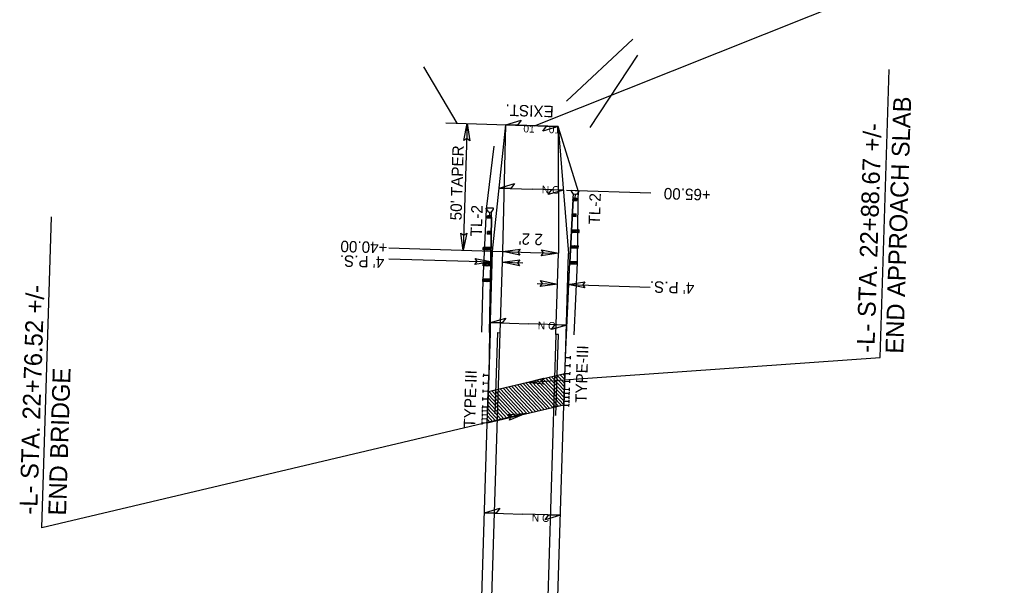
# Model space of a CAD drawing. Extents: x 1515198 to 1515601, y 565062 to 565830.
# Drawn here: x 1515204.5 to 1515593.5, y 565342 to 565565 of the extents above; entities that cross this region are included whole.
import ezdxf

# ---------------------------------------------------------------- set-up
doc = ezdxf.new("R2010")
doc.units = 0
for name, color, linetype in [('Default', 7, 'Continuous'), ('Old_Level_1', 7, 'Continuous'), ('Old_Level_3', 7, 'Continuous'), ('Prop Approach Slab', 7, 'Continuous'), ('Prop Approach Slab Hatching', 7, 'Continuous'), ('Prop Dimension', 7, 'Continuous'), ('Prop Dimension Text', 7, 'Continuous'), ('Prop EOT', 7, 'Continuous'), ('Prop Guardrail', 7, 'Continuous'), ('Prop Guardrail Anchor Unit CELL', 7, 'Continuous'), ('Prop Horizontal Alignment Curve and Spiral Data', 7, 'Continuous'), ('Prop Horizontal Alignment Tick Small', 7, 'Continuous'), ('Prop Lane Lines', 7, 'Continuous'), ('Prop Paved Shoulder', 7, 'Continuous'), ('Prop Roadway Bridge', 7, 'Continuous'), ('Prop SBG', 7, 'Continuous'), ('Prop Structure Anchor Unit CELL', 7, 'Continuous'), ('Prop Superelevation  Arrow CELL', 7, 'Continuous'), ('Prop Superelevation Label', 7, 'Continuous'), ('Prop Terminator CELL', 7, 'Continuous')]:
    doc.layers.add(name, color=color, linetype=linetype)

msp = doc.modelspace()

# ---------------------------------------------------------------- linework, layer by layer
at = {"layer": 'Default'}
msp.add_lwpolyline([(1515421.77, 565431.67), (1515419.93, 565431.83), (1515419.74, 565432.08)], dxfattribs=at)
at = {"layer": 'Old_Level_1'}
for p, q in [((1515424.77, 565497.19), (1515416.89, 565522.45)), ((1515388.56, 565490.28), (1515391.55, 565515.2)), ((1515424.39, 565469.19), (1515424.68, 565494.19)), ((1515424.68, 565494.19), (1515424.77, 565497.19)), ((1515388.46, 565487.28), (1515388.56, 565490.28)), ((1515387.18, 565462.31), (1515388.46, 565487.28)), ((1515423.07, 565440.7), (1515424.39, 565469.19)), ((1515386.76, 565441.84), (1515387.18, 565462.31))]:
    msp.add_line(p, q, dxfattribs=at)
at = {"layer": 'Old_Level_3'}
for p, q in [((1515421.41, 565469.28), (1515422.69, 565494.25)), ((1515390.17, 565462.22), (1515390.45, 565487.21)), ((1515420.08, 565440.79), (1515421.41, 565469.28)), ((1515389.75, 565441.74), (1515390.17, 565462.22)), ((1515390.17, 565462.22), (1515390.17, 565462.22))]:
    msp.add_line(p, q, dxfattribs=at)
at = {"layer": 'Prop Approach Slab'}
msp.add_lwpolyline([(1515388.83, 565405.98), (1515389.22, 565418.4), (1515419.45, 565425.49), (1515419.06, 565413.07)], close=True, dxfattribs=at)
at = {"layer": 'Prop Approach Slab Hatching'}
for p, q in [((1515419.11, 565414.63), (1515410.82, 565423.47)), ((1515419.16, 565416.05), (1515411.94, 565423.73)), ((1515419.2, 565417.46), (1515413.07, 565423.99)), ((1515419.25, 565418.87), (1515414.19, 565424.26)), ((1515419.29, 565420.29), (1515415.31, 565424.52)), ((1515419.33, 565421.7), (1515416.44, 565424.78)), ((1515419.38, 565423.11), (1515417.56, 565425.05)), ((1515419.42, 565424.53), (1515418.69, 565425.31)), ((1515403.44, 565409.41), (1515393.96, 565419.51)), ((1515404.57, 565409.67), (1515395.08, 565419.77)), ((1515405.69, 565409.94), (1515396.2, 565420.04)), ((1515406.81, 565410.2), (1515397.33, 565420.3)), ((1515407.94, 565410.46), (1515398.45, 565420.56)), ((1515409.06, 565410.73), (1515399.58, 565420.83)), ((1515410.19, 565410.99), (1515400.7, 565421.09)), ((1515411.31, 565411.26), (1515401.82, 565421.36)), ((1515412.43, 565411.52), (1515402.95, 565421.62)), ((1515413.56, 565411.78), (1515404.07, 565421.88)), ((1515414.68, 565412.05), (1515405.2, 565422.15)), ((1515415.81, 565412.31), (1515406.32, 565422.41)), ((1515416.93, 565412.57), (1515407.45, 565422.67)), ((1515418.06, 565412.84), (1515408.57, 565422.94)), ((1515419.07, 565413.22), (1515409.69, 565423.2)), ((1515396.7, 565407.83), (1515389.14, 565415.87)), ((1515397.82, 565408.09), (1515389.18, 565417.29)), ((1515398.94, 565408.35), (1515389.46, 565418.45)), ((1515400.07, 565408.62), (1515390.58, 565418.72)), ((1515401.19, 565408.88), (1515391.71, 565418.98)), ((1515402.32, 565409.15), (1515392.83, 565419.25)), ((1515393.32, 565407.03), (1515389, 565411.63)), ((1515394.45, 565407.3), (1515389.05, 565413.05)), ((1515395.57, 565407.56), (1515389.09, 565414.46)), ((1515391.08, 565406.51), (1515388.92, 565408.81)), ((1515392.2, 565406.77), (1515388.96, 565410.22)), ((1515389.95, 565406.24), (1515388.87, 565407.39))]:
    msp.add_line(p, q, dxfattribs=at)
at = {"layer": 'Prop Dimension'}
for p, q in [((1515372.53, 565524.32), (1515416.85, 565522.93)), ((1515380.92, 565524.06), (1515379.35, 565474.08)), ((1515420.03, 565497.82), (1515453.36, 565496.78)), ((1515350.07, 565475), (1515394.95, 565473.6)), ((1515350.07, 565470.78), (1515390.82, 565469.5)), ((1515394.95, 565473.6), (1515405.94, 565473.25)), ((1515405.94, 565473.25), (1515416.94, 565472.91)), ((1515394.82, 565469.38), (1515402.81, 565469.13)), ((1515408.56, 565461.01), (1515416.56, 565460.76)), ((1515420.55, 565460.64), (1515453.02, 565459.62))]:
    msp.add_line(p, q, dxfattribs=at)
at = {"layer": 'Prop EOT'}
for p, q in [((1515394.95, 565473.6), (1515396.21, 565523.58)), ((1515416.85, 565522.93), (1515396.21, 565523.58)), ((1515416.85, 565522.93), (1515416.94, 565472.91)), ((1515393.95, 565441.61), (1515394.95, 565473.6)), ((1515415.94, 565440.92), (1515416.94, 565472.91)), ((1515391.94, 565409.66), (1515392.95, 565441.64)), ((1515392.95, 565441.64), (1515393.95, 565441.61)), ((1515415.93, 565408.91), (1515416.93, 565440.89)), ((1515416.93, 565440.89), (1515415.94, 565440.92))]:
    msp.add_line(p, q, dxfattribs=at)
at = {"layer": 'Prop Guardrail'}
for p, q in [((1515419.93, 565440.8), (1515421.4, 565469.28)), ((1515390.18, 565462.21), (1515389.95, 565441.74)), ((1515389.95, 565441.74), (1515389.41, 565424.72)), ((1515419.65, 565431.82), (1515419.93, 565440.8))]:
    msp.add_line(p, q, dxfattribs=at)
at = {"layer": 'Prop Guardrail Anchor Unit CELL'}
for p, q in [((1515420.04, 565532.84), (1515446.25, 565557.32)), ((1515429.48, 565522.54), (1515448.17, 565551.03)), ((1515377, 565524.18), (1515363.88, 565546.42)), ((1515422, 565497.43), (1515422.01, 565497.74)), ((1515422.79, 565496.21), (1515422, 565497.43)), ((1515422.01, 565497.74), (1515424.95, 565497.59)), ((1515424.93, 565497.28), (1515424.02, 565496.15)), ((1515424.93, 565497.28), (1515424.95, 565497.59)), ((1515422.68, 565494.25), (1515421.4, 565469.28)), ((1515422.65, 565493.75), (1515422.7, 565494.75)), ((1515422.65, 565493.75), (1515424.22, 565494.67)), ((1515422.65, 565493.75), (1515424.17, 565493.67)), ((1515422.7, 565494.75), (1515424.22, 565494.67)), ((1515424.17, 565493.67), (1515422.7, 565494.75)), ((1515422.71, 565494.74), (1515422.79, 565496.21)), ((1515424.02, 565496.15), (1515422.79, 565496.21)), ((1515423.51, 565496.18), (1515423.43, 565494.71)), ((1515424.17, 565493.67), (1515424.22, 565494.67)), ((1515391.35, 565490.66), (1515388.41, 565490.69)), ((1515388.41, 565490.38), (1515388.41, 565490.69)), ((1515388.41, 565490.38), (1515389.25, 565489.2)), ((1515390.47, 565489.18), (1515391.35, 565490.35)), ((1515391.35, 565490.35), (1515391.35, 565490.66)), ((1515388.94, 565486.73), (1515388.95, 565487.73)), ((1515388.94, 565486.73), (1515390.47, 565487.71)), ((1515390.46, 565486.71), (1515388.94, 565486.73)), ((1515390.47, 565487.71), (1515388.95, 565487.73)), ((1515390.46, 565486.71), (1515388.95, 565487.73)), ((1515389.25, 565489.2), (1515390.47, 565489.18)), ((1515389.75, 565489.19), (1515389.74, 565487.72)), ((1515390.46, 565487.21), (1515390.18, 565462.21)), ((1515390.46, 565487.71), (1515390.47, 565489.18)), ((1515390.46, 565486.71), (1515390.47, 565487.71)), ((1515422.33, 565487.5), (1515422.38, 565488.5)), ((1515422.33, 565487.5), (1515423.9, 565488.43)), ((1515422.33, 565487.5), (1515423.85, 565487.43)), ((1515422.38, 565488.5), (1515423.9, 565488.43)), ((1515423.85, 565487.43), (1515422.38, 565488.5)), ((1515423.85, 565487.43), (1515423.9, 565488.43)), ((1515422.01, 565481.26), (1515422.06, 565482.26)), ((1515422.01, 565481.26), (1515423.58, 565482.18)), ((1515422.06, 565482.26), (1515425.09, 565482.11)), ((1515423.53, 565481.19), (1515422.06, 565482.26)), ((1515423.53, 565481.19), (1515423.58, 565482.18)), ((1515425.09, 565482.11), (1515423.53, 565481.19)), ((1515423.58, 565482.18), (1515425.04, 565481.11)), ((1515425.04, 565481.11), (1515425.09, 565482.11)), ((1515388.87, 565480.48), (1515388.88, 565481.48)), ((1515388.87, 565480.48), (1515390.4, 565481.46)), ((1515390.39, 565480.46), (1515388.87, 565480.48)), ((1515390.4, 565481.46), (1515388.88, 565481.48)), ((1515390.39, 565480.46), (1515388.88, 565481.48)), ((1515390.39, 565480.46), (1515390.4, 565481.46)), ((1515422.01, 565481.26), (1515425.04, 565481.11)), ((1515387.28, 565474.25), (1515387.29, 565475.25)), ((1515388.81, 565475.23), (1515387.28, 565474.25)), ((1515390.32, 565474.21), (1515387.28, 565474.25)), ((1515390.33, 565475.21), (1515387.29, 565475.25)), ((1515387.29, 565475.25), (1515388.8, 565474.23)), ((1515388.8, 565474.23), (1515388.81, 565475.23)), ((1515388.8, 565474.23), (1515390.33, 565475.21)), ((1515390.32, 565474.21), (1515388.81, 565475.23)), ((1515390.32, 565474.21), (1515390.33, 565475.21)), ((1515421.69, 565475.02), (1515421.74, 565476.02)), ((1515421.69, 565475.02), (1515423.26, 565475.94)), ((1515421.69, 565475.02), (1515424.72, 565474.87)), ((1515421.74, 565476.02), (1515424.77, 565475.86)), ((1515423.21, 565474.94), (1515421.74, 565476.02)), ((1515423.21, 565474.94), (1515423.26, 565475.94)), ((1515424.77, 565475.86), (1515423.21, 565474.94)), ((1515423.26, 565475.94), (1515424.72, 565474.87)), ((1515424.72, 565474.87), (1515424.77, 565475.86)), ((1515387.21, 565468), (1515387.22, 565469)), ((1515388.74, 565468.98), (1515387.21, 565468)), ((1515390.25, 565467.96), (1515387.21, 565468)), ((1515390.26, 565468.96), (1515387.22, 565469)), ((1515387.22, 565469), (1515388.73, 565467.98)), ((1515388.73, 565467.98), (1515388.74, 565468.98)), ((1515388.73, 565467.98), (1515390.26, 565468.96)), ((1515390.25, 565467.96), (1515388.74, 565468.98)), ((1515390.25, 565467.96), (1515390.26, 565468.96)), ((1515421.37, 565468.78), (1515421.42, 565469.78)), ((1515421.37, 565468.78), (1515422.94, 565469.7)), ((1515421.37, 565468.78), (1515424.4, 565468.62)), ((1515421.42, 565469.78), (1515424.45, 565469.62)), ((1515422.89, 565468.7), (1515421.42, 565469.78)), ((1515422.89, 565468.7), (1515422.94, 565469.7)), ((1515424.45, 565469.62), (1515422.89, 565468.7)), ((1515422.94, 565469.7), (1515424.4, 565468.62)), ((1515424.4, 565468.62), (1515424.45, 565469.62)), ((1515387.14, 565461.75), (1515387.15, 565462.75)), ((1515388.67, 565462.73), (1515387.14, 565461.75)), ((1515390.19, 565462.72), (1515387.15, 565462.75)), ((1515387.15, 565462.75), (1515388.66, 565461.73)), ((1515388.66, 565461.73), (1515388.67, 565462.73)), ((1515388.66, 565461.73), (1515390.19, 565462.72)), ((1515390.17, 565461.71), (1515388.67, 565462.73)), ((1515390.17, 565461.71), (1515390.19, 565462.72)), ((1515390.17, 565461.71), (1515387.14, 565461.75))]:
    msp.add_line(p, q, dxfattribs=at)
at = {"layer": 'Prop Horizontal Alignment Tick Small'}
for p, q in [((1515407.51, 565523.23), (1515593.52, 565597.34)), ((1515543.74, 565431.88), (1515547.3, 565545.43)), ((1515213.19, 565364.68), (1515217.04, 565487.34)), ((1515404.34, 565421.94), (1515543.74, 565431.88)), ((1515403.95, 565409.8), (1515213.19, 565364.68))]:
    msp.add_line(p, q, dxfattribs=at)
at = {"layer": 'Prop Lane Lines'}
for p, q in [((1515387.31, 565229.87), (1515393.95, 565441.61)), ((1515415.94, 565440.92), (1515409.48, 565235.07))]:
    msp.add_line(p, q, dxfattribs=at)
at = {"layer": 'Prop Paved Shoulder'}
for p, q in [((1515390.95, 565473.72), (1515396.21, 565523.58)), ((1515416.85, 565522.93), (1515420.94, 565472.78)), ((1515389.95, 565441.74), (1515390.95, 565473.72)), ((1515419.93, 565440.8), (1515420.94, 565472.78))]:
    msp.add_line(p, q, dxfattribs=at)
at = {"layer": 'Prop Roadway Bridge'}
for p, q in [((1515383.79, 565245.35), (1515388.95, 565410)), ((1515413.78, 565244.42), (1515418.94, 565409.06))]:
    msp.add_line(p, q, dxfattribs=at)
at = {"layer": 'Prop SBG'}
for p, q in [((1515389.75, 565441.74), (1515389.4, 565424.72)), ((1515419.66, 565431.81), (1515420.08, 565440.79)), ((1515418.95, 565408.96), (1515419.66, 565431.82)), ((1515389.4, 565424.72), (1515388.94, 565409.9))]:
    msp.add_line(p, q, dxfattribs=at)
at = {"layer": 'Prop Structure Anchor Unit CELL'}
for p, q in [((1515419.06, 565413.07), (1515419.65, 565431.82)), ((1515419.65, 565431.82), (1515421.65, 565431.75)), ((1515421.63, 565431.18), (1515421.67, 565432.33)), ((1515419.55, 565428.69), (1515421.55, 565428.63)), ((1515421.53, 565428.06), (1515421.57, 565429.2)), ((1515387.4, 565424.21), (1515387.43, 565425.36)), ((1515389.41, 565424.72), (1515387.42, 565424.78)), ((1515388.83, 565405.98), (1515389.41, 565424.72)), ((1515419.46, 565425.57), (1515421.46, 565425.51)), ((1515421.44, 565424.93), (1515421.47, 565426.08)), ((1515387.3, 565421.09), (1515387.34, 565422.23)), ((1515389.32, 565421.6), (1515387.32, 565421.66)), ((1515419.36, 565422.44), (1515421.36, 565422.38)), ((1515421.24, 565418.69), (1515421.28, 565419.83)), ((1515421.34, 565421.81), (1515421.38, 565422.95)), ((1515387.1, 565414.84), (1515387.14, 565415.99)), ((1515387.2, 565417.96), (1515387.24, 565419.11)), ((1515389.22, 565418.47), (1515387.22, 565418.54)), ((1515419.16, 565416.2), (1515421.16, 565416.14)), ((1515419.21, 565417.76), (1515421.21, 565417.7)), ((1515419.26, 565419.32), (1515421.26, 565419.26)), ((1515421.14, 565415.56), (1515421.18, 565416.71)), ((1515421.19, 565417.12), (1515421.23, 565418.27)), ((1515387.01, 565411.72), (1515387.04, 565412.86)), ((1515389.02, 565412.23), (1515387.02, 565412.29)), ((1515389.12, 565415.35), (1515387.12, 565415.41)), ((1515419.06, 565413.07), (1515421.06, 565413.01)), ((1515419.11, 565414.64), (1515421.11, 565414.57)), ((1515421.05, 565412.44), (1515421.08, 565413.58)), ((1515421.09, 565414), (1515421.13, 565415.15)), ((1515386.86, 565407.03), (1515386.9, 565408.18)), ((1515386.91, 565408.59), (1515386.94, 565409.74)), ((1515388.93, 565409.1), (1515386.93, 565409.17)), ((1515386.96, 565410.16), (1515386.99, 565411.3)), ((1515388.97, 565410.66), (1515386.98, 565410.73)), ((1515386.81, 565405.47), (1515386.85, 565406.61)), ((1515388.83, 565405.98), (1515386.83, 565406.04)), ((1515388.88, 565407.54), (1515386.88, 565407.6))]:
    msp.add_line(p, q, dxfattribs=at)
at = {"layer": 'Prop Superelevation  Arrow CELL'}
for p, q in [((1515396.13, 565523.58), (1515407.51, 565523.23)), ((1515416.85, 565522.93), (1515407.51, 565523.23)), ((1515393.58, 565498.65), (1515406.73, 565498.24)), ((1515418.89, 565497.86), (1515406.73, 565498.24)), ((1515390.07, 565445.57), (1515405.06, 565445.1)), ((1515420.19, 565444.63), (1515405.06, 565445.1)), ((1515387.72, 565370.54), (1515402.71, 565370.07)), ((1515417.7, 565369.6), (1515402.71, 565370.07))]:
    msp.add_line(p, q, dxfattribs=at)
for points in [[(1515396.13, 565523.58), (1515402.19, 565525.39), (1515400.75, 565523.44)], [(1515416.85, 565522.93), (1515410.79, 565521.12), (1515412.23, 565523.08)], [(1515393.58, 565498.65), (1515399.64, 565500.46), (1515398.2, 565498.51)], [(1515418.89, 565497.86), (1515412.83, 565496.05), (1515414.27, 565498)], [(1515390.07, 565445.57), (1515396.13, 565447.38), (1515394.69, 565445.43)], [(1515420.19, 565444.63), (1515414.13, 565442.82), (1515415.56, 565444.77)], [(1515387.72, 565370.54), (1515393.78, 565372.36), (1515392.34, 565370.4)], [(1515417.7, 565369.6), (1515411.64, 565367.79), (1515413.08, 565369.75)]]:
    msp.add_lwpolyline(points, close=True, dxfattribs=at)
at = {"layer": 'Prop Terminator CELL'}
for points in [[(1515379.54, 565517.35), (1515380.92, 565524.06), (1515381.91, 565517.24), (1515380.73, 565518.14)], [(1515380.73, 565480.8), (1515379.35, 565474.08), (1515378.37, 565480.91), (1515379.54, 565480.01)], [(1515401.66, 565472.22), (1515394.95, 565473.6), (1515401.77, 565474.58), (1515400.87, 565473.41)], [(1515410.23, 565474.28), (1515416.94, 565472.91), (1515410.12, 565471.92), (1515411.02, 565473.09)], [(1515384.11, 565470.88), (1515390.82, 565469.5), (1515384, 565468.52), (1515384.9, 565469.69)], [(1515401.53, 565468), (1515394.82, 565469.38), (1515401.64, 565470.36), (1515400.74, 565469.19)], [(1515409.85, 565462.13), (1515416.56, 565460.76), (1515409.74, 565459.77), (1515410.63, 565460.95)], [(1515427.27, 565459.26), (1515420.55, 565460.64), (1515427.38, 565461.62), (1515426.48, 565460.45)], [(1515411.15, 565421.26), (1515404.34, 565421.94), (1515411.02, 565423.62), (1515410.25, 565422.37)], [(1515397.12, 565409.38), (1515403.95, 565409.8), (1515397.63, 565407.07), (1515398.19, 565408.44)]]:
    msp.add_lwpolyline(points, close=True, dxfattribs=at)

# ---------------------------------------------------------------- texts
at = {"layer": 'Prop Dimension Text'}
for s, rotation, p in [('EXIST.', 178.205, (1515415.14, 565531.01)), ("50' TAPER", 88.205, (1515378.69, 565485.84)), ('+65.00', 178.205, (1515477.09, 565498.14)), ('TL-2', 88.205, (1515433.27, 565484.19)), ('TL-2', 88.205, (1515386.67, 565479.52)), ('+40.00', 178.205, (1515349.57, 565477.33)), ("2 2'", 178.205, (1515410.81, 565480.56)), ("4' P.S.", 178.205, (1515348.27, 565471.63)), ("4' P.S.", 178.205, (1515470.55, 565461.39)), ('TYPE-III', 88.205, (1515428.01, 565413.82)), ('TYPE-III', 88.205, (1515384.02, 565404.06))]:
    msp.add_text(s, height=4.5, rotation=rotation, dxfattribs=at).set_placement(p)
at = {"layer": 'Prop Horizontal Alignment Curve and Spiral Data'}
for s, p in [('END APPROACH SLAB', (1515552.86, 565433.26)), ('-L- STA. 22+88.67 +/-', (1515541.49, 565433.62)), ('-L- STA. 22+76.52 +/-', (1515211.33, 565369.81)), ('END BRIDGE', (1515222.7, 565369.45))]:
    msp.add_text(s, height=7, rotation=88.205, dxfattribs=at).set_placement(p)
at = {"layer": 'Prop Superelevation Label'}
for s, p in [('01', (1515403.03, 565520.6)), ('01', (1515413.06, 565520.28)), ('N C', (1515410.31, 565496.58)), ('N C', (1515408.74, 565443)), ('N C', (1515406.36, 565367.19))]:
    msp.add_text(s, height=3, rotation=358.205, dxfattribs=at).set_placement(p)

doc.saveas('drawing.dxf')
